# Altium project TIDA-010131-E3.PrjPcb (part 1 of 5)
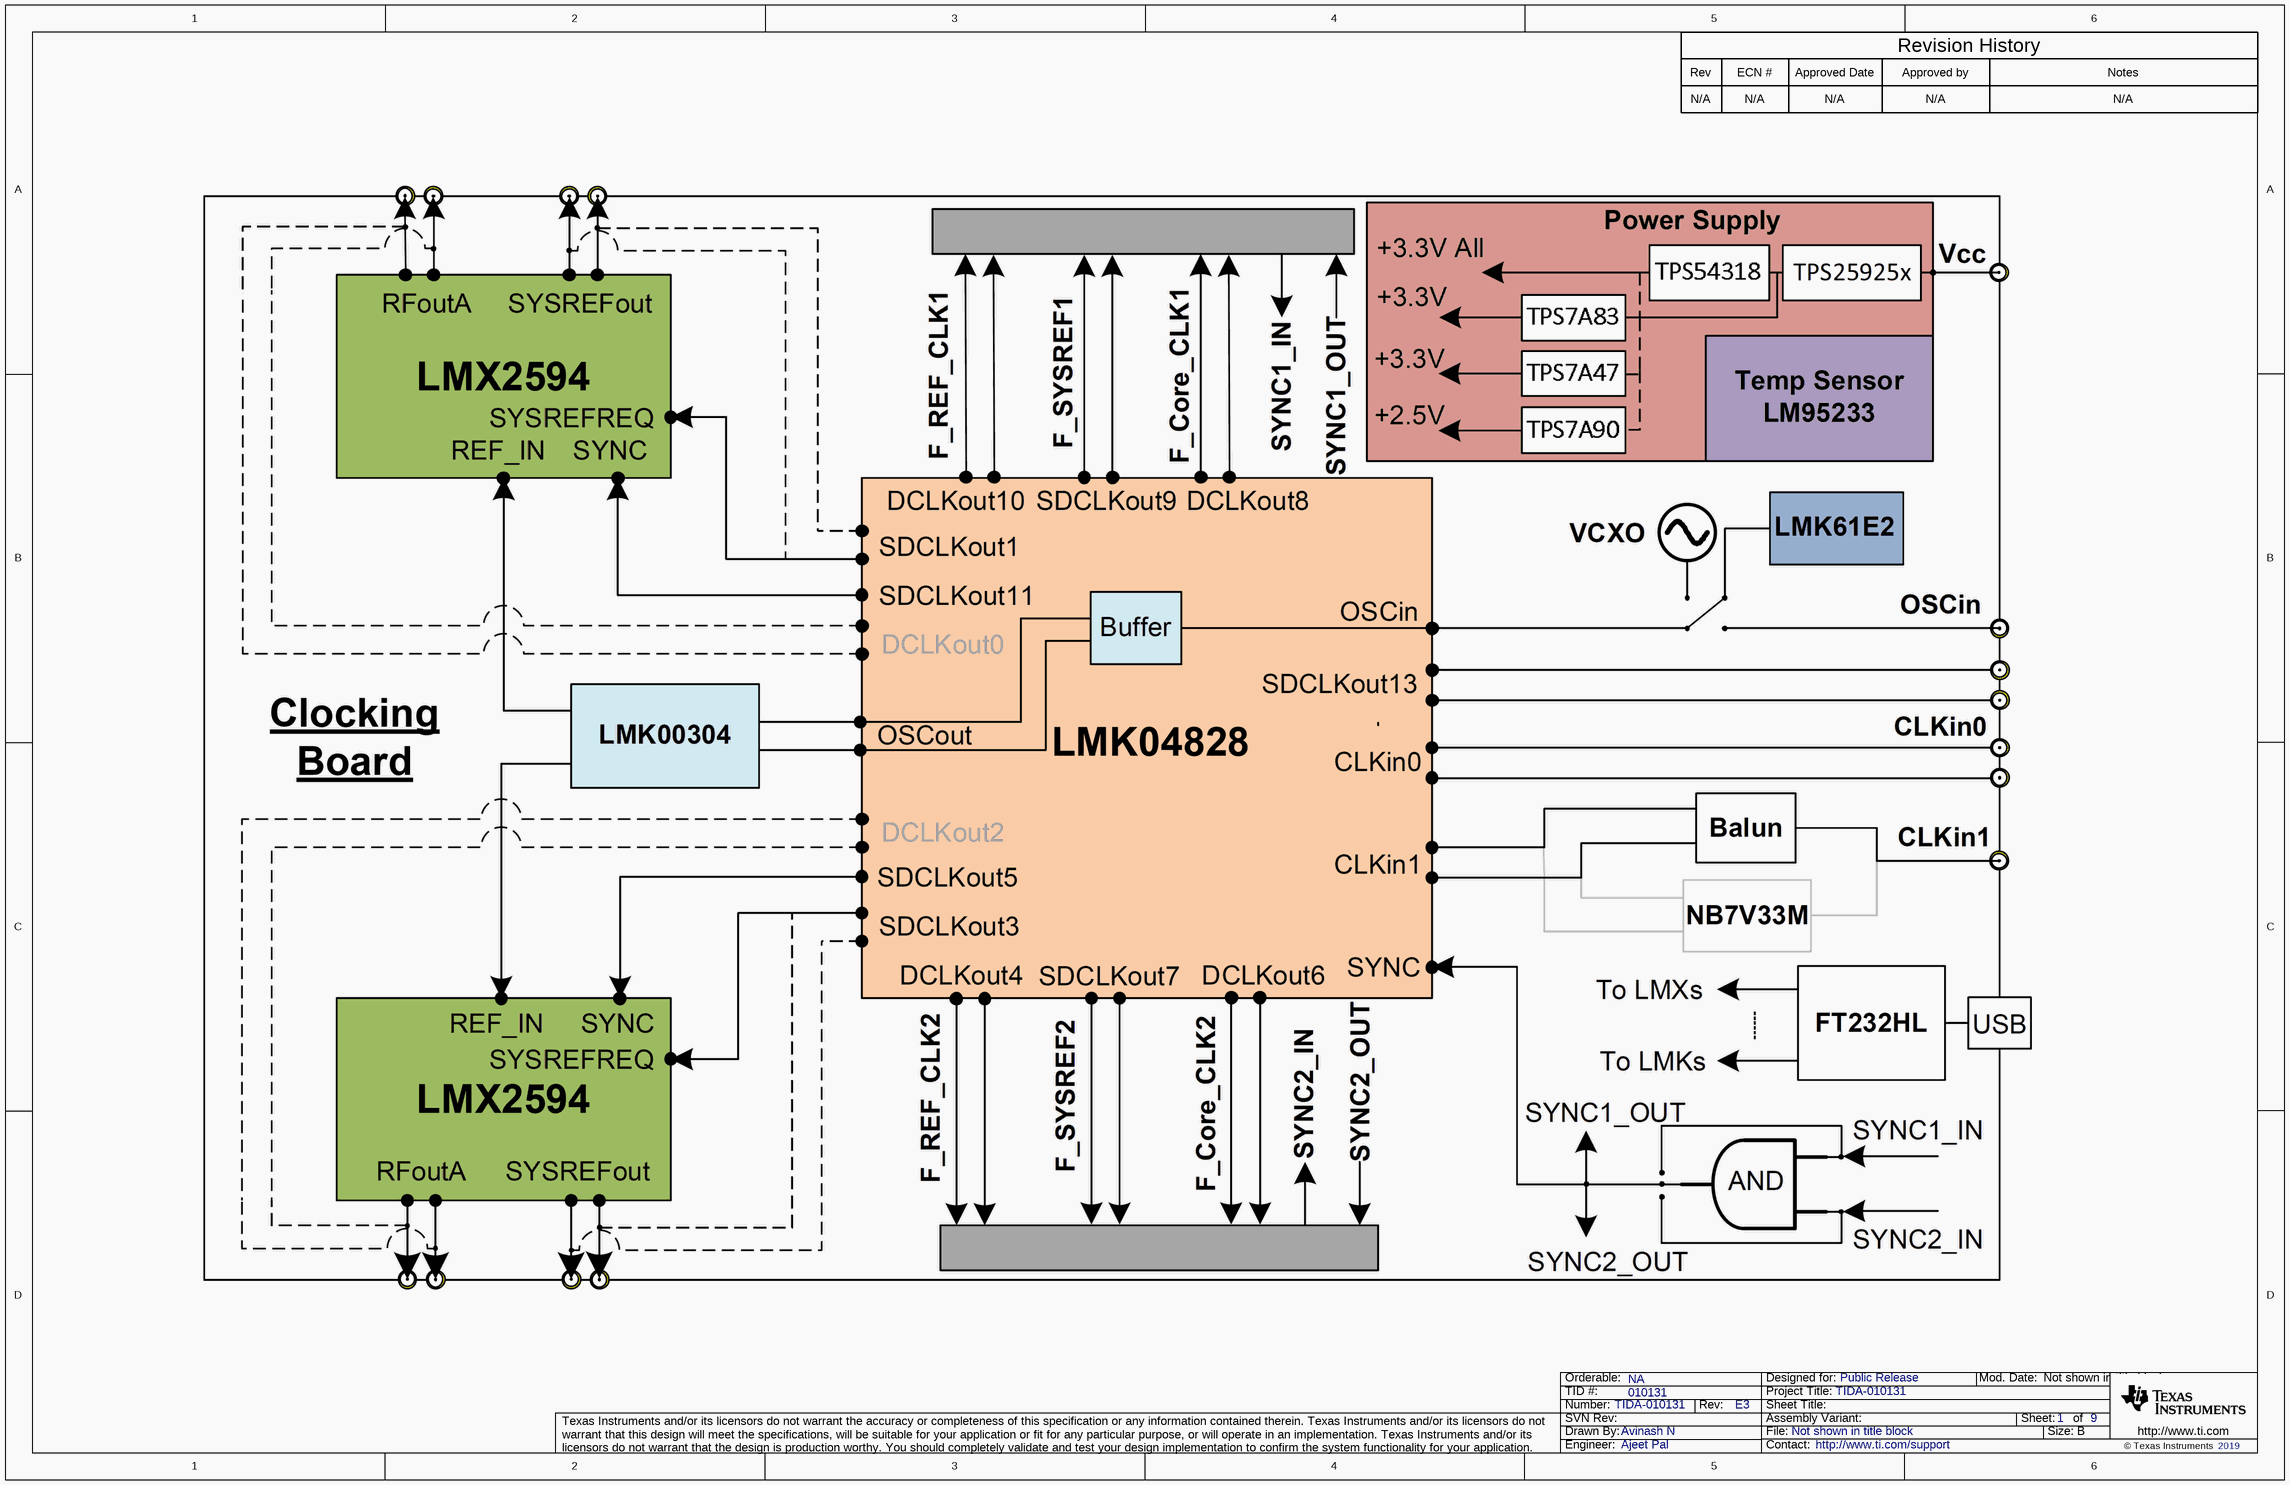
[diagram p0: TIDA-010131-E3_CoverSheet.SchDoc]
CopyrightYear: 2019; EVM_orderable: NA; PCB_Layout: Avinash N; PCB_Rev: E3; PRJ_Customer: Public Release; PRJ_Engineer: Ajeet Pal; PRJ_Number: TIDA-010131; PRJ_Title: TIDA-010131; SCH_Rev: E3; TechSupport: http://www.ti.com/support; TID: 010131
9 sheets, 759 parts. Net scope: flat (ports and power ports of the same name join across sheets).
Board file: TIDA-010131-E3.PcbDoc
Sheets:
  TIDA-010131-E3_CoverSheet.SchDoc
  TIDA-010131-E3_LMK0482x.SchDoc
  TIDA-010131-E3_LMK0482x _CLK_PWR.SchDoc
  TIDA-010131-E3_LMK00304_Buffer.SchDoc
  TIDA-010131-E3_LMX2594R_1.SchDoc
  TIDA-010131-E3_LMX2594R_2.SchDoc
  TIDA-010131-E3_USB.SchDoc
  TIDA-010131-E3_POWER SUPPLIES.SchDoc
  TIDA-010131-E3_Hardware.SchDoc

## Sheet TIDA-010131-E3_CoverSheet.SchDoc
size 431 x 279 mm; Date: Not shown in title block; ApprovedBy: Not shown in title block; CheckedBy: Not shown in title block; Author: Not shown in title block; CompanyName: Not shown in title block; DrawnBy: Avinash N; Engineer: Not shown in title block; Organization: Not shown in title block; Address1: Not shown in title block; Address2: Not shown in title block; Address3: Not shown in title block; Address4: Not shown in title block; DocumentNumber: 1; Revision: Use project parameter SCH_Rev; SheetNumber: 1; SheetTotal: 9; PageSetup: Record=PageOptions¦CenterHorizontal=True¦CenterVertical=True¦PrintScale=1.00¦XCorrection=1.00¦YCorrection=1.00¦PrintKind=0¦BorderSize=5000000¦LeftOffset=0¦BottomOffset=0¦Orientation=2¦PaperLength=1000¦PaperWidth=1000¦Scale=100¦PaperSource=15¦PrintQuality=600¦MediaType=1¦DitherType=10¦PaperKind=Letter¦PrintScaleMode=1

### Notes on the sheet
- Rev
- N/A
- ECN #
- Approved Date
- Approved by
- Revision History
- Notes

## Sheet TIDA-010131-E3_LMK0482x.SchDoc: LMK0482x
size 431 x 279 mm; Date: Not shown in title block; ApprovedBy: Not shown in title block; CheckedBy: Not shown in title block; Author: Not shown in title block; CompanyName: Not shown in title block; DrawnBy: Avinash N; Engineer: Not shown in title block; Organization: Not shown in title block; Address1: Not shown in title block; Address2: Not shown in title block; Address3: Not shown in title block; Address4: Not shown in title block; DocumentNumber: 1; Revision: Use project parameter SCH_Rev; SheetNumber: 2; SheetTotal: 9; PageSetup: Record=PageOptions¦CenterHorizontal=True¦CenterVertical=True¦PrintScale=1.00¦XCorrection=1.00¦YCorrection=1.00¦PrintKind=0¦BorderSize=5000000¦LeftOffset=0¦BottomOffset=0¦Orientation=2¦PaperLength=1000¦PaperWidth=1000¦Scale=100¦PaperSource=15¦PrintQuality=600¦MediaType=1¦DitherType=10¦PaperKind=Letter¦PrintScaleMode=1
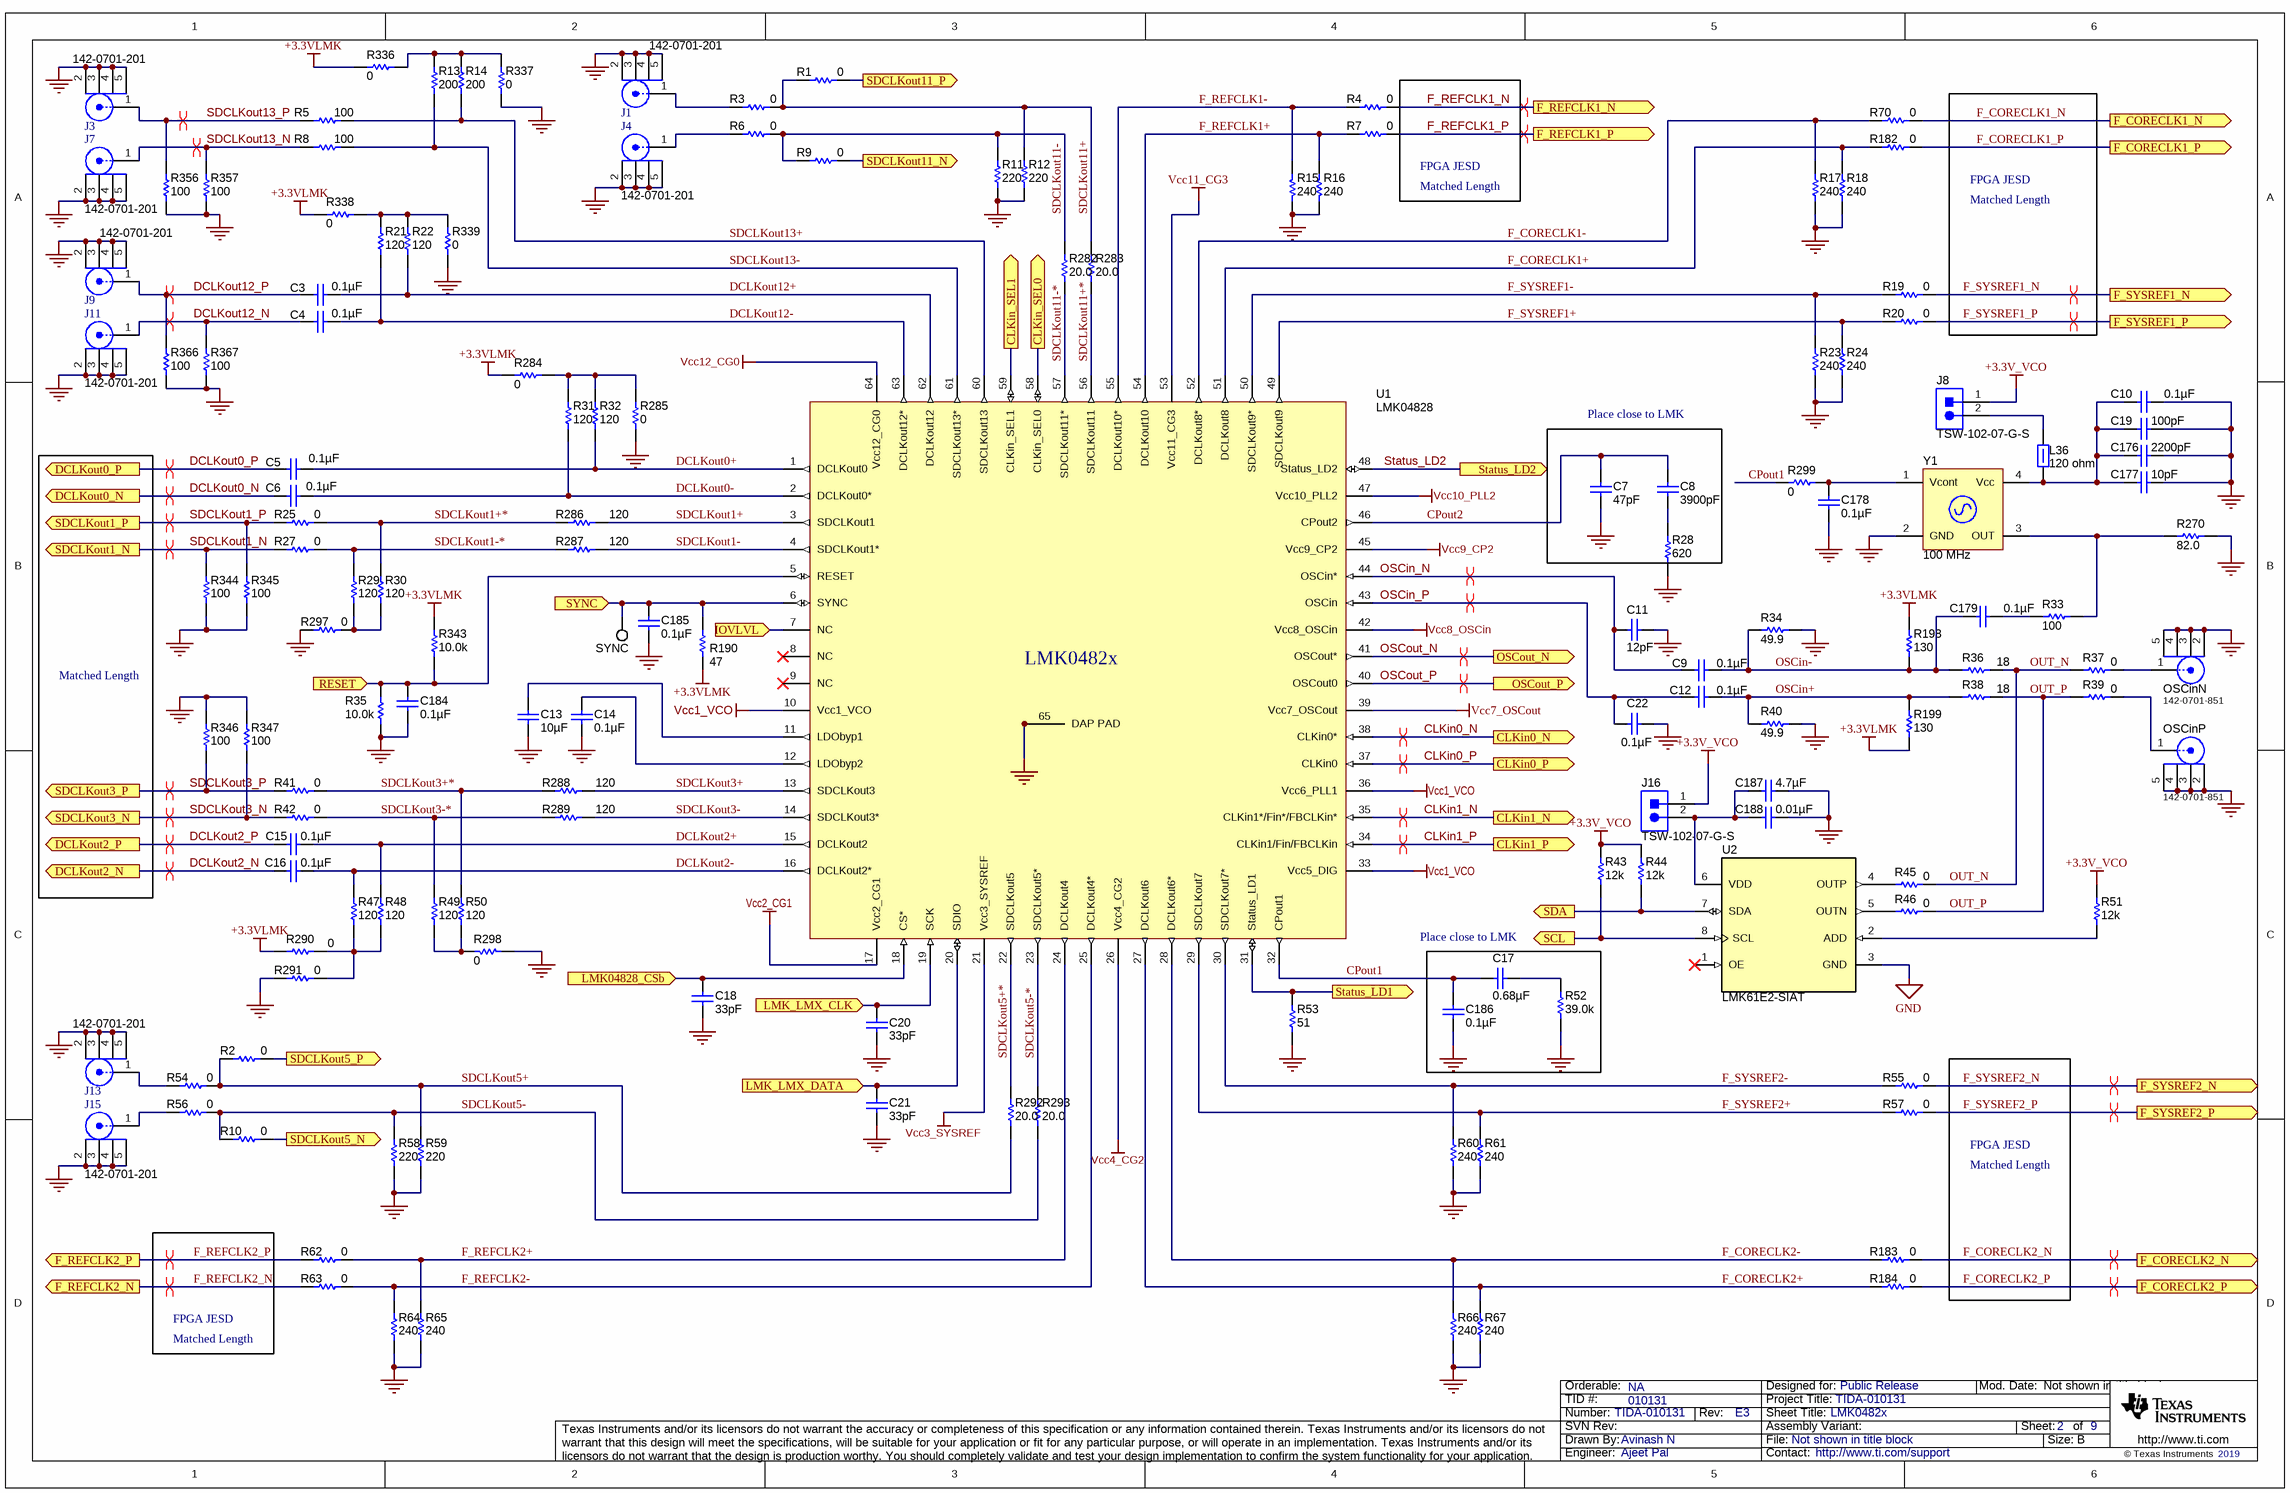
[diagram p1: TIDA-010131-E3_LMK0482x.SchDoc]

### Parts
C3  ValueDisplayed: 0.1µF  [0402]  (hidden comment: C1005X7R1E104M050BB)
C4  ValueDisplayed: 0.1µF  [0402]  (hidden comment: C1005X7R1E104M050BB)
C5  ValueDisplayed: 0.1µF  [0402]  (hidden comment: C1005X7R1E104M050BB)
C6  ValueDisplayed: 0.1µF  [0402]  (hidden comment: C1005X7R1E104M050BB)
C7  ValueDisplayed: 47pF  [0201_033]  (hidden comment: GRM0335C1E470JA01D)
C8  ValueDisplayed: 3900pF  [0201]  (hidden comment: 0201ZD392KAT2A)
C9  ValueDisplayed: 0.1µF  [0402]  (hidden comment: C1005X7R1E104M050BB)
C10  ValueDisplayed: 0.1µF  [0402]  (hidden comment: C1005X7R1E104M050BB)
C11  ValueDisplayed: 12pF  [0402]  (hidden comment: C0402C120J3GACAUTO)
C12  ValueDisplayed: 0.1µF  [0402]  (hidden comment: C1005X7R1E104M050BB)
C13  ValueDisplayed: 10µF  [0805_HV]  (hidden comment: C0805C106K8PACTU)
C14  ValueDisplayed: 0.1µF  [0603]  (hidden comment: C0603C104J3RACTU)
C15  ValueDisplayed: 0.1µF  [0402]  (hidden comment: C1005X7R1E104M050BB)
C16  ValueDisplayed: 0.1µF  [0402]  (hidden comment: C1005X7R1E104M050BB)
C17  ValueDisplayed: 0.68µF  [0402]  (hidden comment: C1005X5R1A684K050BB)
C18  ValueDisplayed: 33pF  [0603L]  (hidden comment: C0603C330J5GACTU)
C19  ValueDisplayed: 100pF  [0402]  (hidden comment: 04025A101FAT2A)
C20  ValueDisplayed: 33pF  [0603L]  (hidden comment: C0603C330J5GACTU)
C21  ValueDisplayed: 33pF  [0603L]  (hidden comment: C0603C330J5GACTU)
C22  ValueDisplayed: 0.1µF  [0402]  (hidden comment: C1005X7R1E104M050BB)
C176  ValueDisplayed: 2200pF  [0402]  (hidden comment: GRM155R71E222KA01D)
C177  ValueDisplayed: 10pF  [0402]  (hidden comment: GRM1555C1H100JA01D)
C178  ValueDisplayed: 0.1µF  [0402]  (hidden comment: C1005X7R1E104M050BB)
C179  ValueDisplayed: 0.1µF  [0402]  (hidden comment: C1005X7R1E104M050BB)
C184  ValueDisplayed: 0.1µF  [0402]  (hidden comment: C1005X7R1E104M050BB)
C185  ValueDisplayed: 0.1µF  [0402]  (hidden comment: C1005X7R1E104M050BB)
C186  ValueDisplayed: 0.1µF  [0402]  (hidden comment: C1005X7R1E104M050BB)
C187  ValueDisplayed: 4.7µF  [0402]  (hidden comment: C1005X5R0J475M050BC)
C188  ValueDisplayed: 0.01µF  [0402]  (hidden comment: GRM155R71E103KA01D)
J1  142-0701-201  [Johnson_142-0701-20x]
J3  142-0701-201  [Johnson_142-0701-20x]
J4  142-0701-201  [Johnson_142-0701-20x]
J7  142-0701-201  [Johnson_142-0701-20x]
J8  TSW-102-07-G-S  [TSW-102-07-G-S]
J9  142-0701-201  [Johnson_142-0701-20x]
J11  142-0701-201  [Johnson_142-0701-20x]
J13  142-0701-201  [Johnson_142-0701-20x]
J15  142-0701-201  [Johnson_142-0701-20x]
J16  TSW-102-07-G-S  [TSW-102-07-G-S]
L36  ValueDisplayed: 120 ohm  [0603]  (hidden comment: BLM18SG121TN1D)
OSCinN  142-0701-851  [EMERSON_142-0701-851]
OSCinP  142-0701-851  [EMERSON_142-0701-851]
R1  ValueDisplayed: 0  [0402]  (hidden comment: CRCW04020000Z0ED)
R2  ValueDisplayed: 0  [0402]  (hidden comment: CRCW04020000Z0ED)
R3  ValueDisplayed: 0  [0402]  (hidden comment: CRCW04020000Z0ED)
R4  ValueDisplayed: 0  [0402]  (hidden comment: CRCW04020000Z0ED)
R5  ValueDisplayed: 100  [0402]  (hidden comment: ERJ-2RKF1000X)
R6  ValueDisplayed: 0  [0402]  (hidden comment: CRCW04020000Z0ED)
R7  ValueDisplayed: 0  [0402]  (hidden comment: CRCW04020000Z0ED)
R8  ValueDisplayed: 100  [0402]  (hidden comment: ERJ-2RKF1000X)
R9  ValueDisplayed: 0  [0402]  (hidden comment: CRCW04020000Z0ED)
R10  ValueDisplayed: 0  [0402]  (hidden comment: CRCW04020000Z0ED)
R11  ValueDisplayed: 220  [0402]  (hidden comment: CRCW0402220RJNED)
R12  ValueDisplayed: 220  [0402]  (hidden comment: CRCW0402220RJNED)
R13  ValueDisplayed: 200  [0402]  (hidden comment: CRCW0402200RFKED)
R14  ValueDisplayed: 200  [0402]  (hidden comment: CRCW0402200RFKED)
R15  ValueDisplayed: 240  [0402]  (hidden comment: CRCW0402240RJNED)
R16  ValueDisplayed: 240  [0402]  (hidden comment: CRCW0402240RJNED)
R17  ValueDisplayed: 240  [0402]  (hidden comment: CRCW0402240RJNED)
R18  ValueDisplayed: 240  [0402]  (hidden comment: CRCW0402240RJNED)
R19  ValueDisplayed: 0  [0402]  (hidden comment: CRCW04020000Z0ED)
R20  ValueDisplayed: 0  [0402]  (hidden comment: CRCW04020000Z0ED)
R21  ValueDisplayed: 120  [0402]  (hidden comment: CRCW0402120RJNED)
R22  ValueDisplayed: 120  [0402]  (hidden comment: CRCW0402120RJNED)
R23  ValueDisplayed: 240  [0402]  (hidden comment: CRCW0402240RJNED)
R24  ValueDisplayed: 240  [0402]  (hidden comment: CRCW0402240RJNED)
R25  ValueDisplayed: 0  [0402]  (hidden comment: CRCW04020000Z0ED)
R27  ValueDisplayed: 0  [0402]  (hidden comment: CRCW04020000Z0ED)
R28  ValueDisplayed: 620  [0201]  (hidden comment: RC0201FR-07620RL)
R29  ValueDisplayed: 120  [0402]  (hidden comment: CRCW0402120RJNED)
R30  ValueDisplayed: 120  [0402]  (hidden comment: CRCW0402120RJNED)
R31  ValueDisplayed: 120  [0402]  (hidden comment: CRCW0402120RJNED)
R32  ValueDisplayed: 120  [0402]  (hidden comment: CRCW0402120RJNED)
R33  ValueDisplayed: 100  [0402]  (hidden comment: CRCW0402100RFKED)
R34  ValueDisplayed: 49.9  [0402]  (hidden comment: CRCW040249R9FKED)
R35  ValueDisplayed: 10.0k  [0402]  (hidden comment: ERJ-2RKF1002X)
R36  ValueDisplayed: 18  [0402]  (hidden comment: CRCW040218R0JNED)
R37  ValueDisplayed: 0  [0402]  (hidden comment: CRCW04020000Z0ED)
R38  ValueDisplayed: 18  [0402]  (hidden comment: CRCW040218R0JNED)
R39  ValueDisplayed: 0  [0402]  (hidden comment: CRCW04020000Z0ED)
R40  ValueDisplayed: 49.9  [0402]  (hidden comment: CRCW040249R9FKED)
R41  ValueDisplayed: 0  [0402]  (hidden comment: CRCW04020000Z0ED)
R42  ValueDisplayed: 0  [0402]  (hidden comment: CRCW04020000Z0ED)
R43  ValueDisplayed: 12k  [0402]  (hidden comment: CRCW040212K0JNED)
R44  ValueDisplayed: 12k  [0402]  (hidden comment: CRCW040212K0JNED)
R45  ValueDisplayed: 0  [0402]  (hidden comment: CRCW04020000Z0ED)
R46  ValueDisplayed: 0  [0402]  (hidden comment: CRCW04020000Z0ED)
R47  ValueDisplayed: 120  [0402]  (hidden comment: CRCW0402120RJNED)
R48  ValueDisplayed: 120  [0402]  (hidden comment: CRCW0402120RJNED)
R49  ValueDisplayed: 120  [0402]  (hidden comment: CRCW0402120RJNED)
R50  ValueDisplayed: 120  [0402]  (hidden comment: CRCW0402120RJNED)
R51  ValueDisplayed: 12k  [0402]  (hidden comment: CRCW040212K0JNED)
R52  ValueDisplayed: 39.0k  [0201]  (hidden comment: RC0201FR-0739KL)
R53  value 51  [0603L]  (hidden comment: CRCW060351R0JNEA)
R54  ValueDisplayed: 0  [0402]  (hidden comment: CRCW04020000Z0ED)
R55  ValueDisplayed: 0  [0402]  (hidden comment: CRCW04020000Z0ED)
R56  ValueDisplayed: 0  [0402]  (hidden comment: CRCW04020000Z0ED)
R57  ValueDisplayed: 0  [0402]  (hidden comment: CRCW04020000Z0ED)
R58  ValueDisplayed: 220  [0402]  (hidden comment: CRCW0402220RJNED)
R59  ValueDisplayed: 220  [0402]  (hidden comment: CRCW0402220RJNED)
R60  ValueDisplayed: 240  [0402]  (hidden comment: CRCW0402240RJNED)
R61  ValueDisplayed: 240  [0402]  (hidden comment: CRCW0402240RJNED)
R62  ValueDisplayed: 0  [0402]  (hidden comment: CRCW04020000Z0ED)
R63  ValueDisplayed: 0  [0402]  (hidden comment: CRCW04020000Z0ED)
R64  ValueDisplayed: 240  [0402]  (hidden comment: CRCW0402240RJNED)
R65  ValueDisplayed: 240  [0402]  (hidden comment: CRCW0402240RJNED)
R66  ValueDisplayed: 240  [0402]  (hidden comment: CRCW0402240RJNED)
R67  ValueDisplayed: 240  [0402]  (hidden comment: CRCW0402240RJNED)
R70  ValueDisplayed: 0  [0402]  (hidden comment: CRCW04020000Z0ED)
R182  ValueDisplayed: 0  [0402]  (hidden comment: CRCW04020000Z0ED)
R183  ValueDisplayed: 0  [0402]  (hidden comment: CRCW04020000Z0ED)
R184  ValueDisplayed: 0  [0402]  (hidden comment: CRCW04020000Z0ED)
R190  ValueDisplayed: 47  [0402]  (hidden comment: CRCW040247R0JNED)
R198  ValueDisplayed: 130  [0402]  (hidden comment: CRCW0402130RFKED)
R199  ValueDisplayed: 130  [0402]  (hidden comment: CRCW0402130RFKED)
R270  ValueDisplayed: 82.0  [0603]  (hidden comment: RC0603FR-0782RL)
R282  ValueDisplayed: 20.0  [0402]  (hidden comment: CRCW040220R0FKED)
R283  ValueDisplayed: 20.0  [0402]  (hidden comment: CRCW040220R0FKED)
R284  ValueDisplayed: 0  [0402]  (hidden comment: CRCW04020000Z0ED)
R285  ValueDisplayed: 0  [0402]  (hidden comment: CRCW04020000Z0ED)
R286  ValueDisplayed: 120  [0402]  (hidden comment: CRCW0402120RJNED)
R287  ValueDisplayed: 120  [0402]  (hidden comment: CRCW0402120RJNED)
R288  ValueDisplayed: 120  [0402]  (hidden comment: CRCW0402120RJNED)
R289  ValueDisplayed: 120  [0402]  (hidden comment: CRCW0402120RJNED)
R290  ValueDisplayed: 0  [0402]  (hidden comment: CRCW04020000Z0ED)
R291  ValueDisplayed: 0  [0402]  (hidden comment: CRCW04020000Z0ED)
R292  ValueDisplayed: 20.0  [0402]  (hidden comment: CRCW040220R0FKED)
R293  ValueDisplayed: 20.0  [0402]  (hidden comment: CRCW040220R0FKED)
R297  ValueDisplayed: 0  [0402]  (hidden comment: CRCW04020000Z0ED)
R298  ValueDisplayed: 0  [0402]  (hidden comment: CRCW04020000Z0ED)
R299  ValueDisplayed: 0  [0402]  (hidden comment: CRCW04020000Z0ED)
R336  ValueDisplayed: 0  [0402]  (hidden comment: CRCW04020000Z0ED)
R337  ValueDisplayed: 0  [0402]  (hidden comment: CRCW04020000Z0ED)
R338  ValueDisplayed: 0  [0402]  (hidden comment: CRCW04020000Z0ED)
R339  ValueDisplayed: 0  [0402]  (hidden comment: CRCW04020000Z0ED)
R343  ValueDisplayed: 10.0k  [0402]  (hidden comment: ERJ-2RKF1002X)
R344  ValueDisplayed: 100  [0402]  (hidden comment: ERJ-2RKF1000X)
R345  ValueDisplayed: 100  [0402]  (hidden comment: ERJ-2RKF1000X)
R346  ValueDisplayed: 100  [0402]  (hidden comment: ERJ-2RKF1000X)
R347  ValueDisplayed: 100  [0402]  (hidden comment: ERJ-2RKF1000X)
R356  ValueDisplayed: 100  [0402]  (hidden comment: ERJ-2RKF1000X)
R357  ValueDisplayed: 100  [0402]  (hidden comment: ERJ-2RKF1000X)
R366  ValueDisplayed: 100  [0402]  (hidden comment: ERJ-2RKF1000X)
R367  ValueDisplayed: 100  [0402]  (hidden comment: ERJ-2RKF1000X)
SYNC  5007  [Keystone5007]  (value not drawn)
U1  LMK04828  [NKD0064A]
U2  LMK61E2-SIAT  [SIA0008B]
Y1  Frequency: 100 MHz  [OSC_CVHD-950-4]  (hidden comment: CVHD-950-100.000)

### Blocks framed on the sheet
Place close to LMK: C7 C8 R28

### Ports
CLKin0_N (out), CLKin0_P (out), CLKin1_N (out), CLKin1_P (out), CLKin_SEL0 (out), CLKin_SEL1 (out), DCLKout0_N (out), DCLKout0_P (out), DCLKout2_N (out), DCLKout2_P (out), F_CORECLK1_N (out), F_CORECLK1_P (out), F_CORECLK2_N (out), F_CORECLK2_P (out), F_REFCLK1_N (out), F_REFCLK1_P (out), F_REFCLK2_N (out), F_REFCLK2_P (out), F_SYSREF1_N (out), F_SYSREF1_P (out), F_SYSREF2_N (out), F_SYSREF2_P (out), IOVLVL (in), LMK04828_CSb (in), LMK_LMX_CLK (in), LMK_LMX_DATA (in), OSCout_N (out), OSCout_P (out), RESET (in), SCL (out), SDA (out), SDCLKout1_N (out), SDCLKout1_P (out), SDCLKout3_N (out), SDCLKout3_P (out), SDCLKout5_N (out), SDCLKout5_P (out), SDCLKout11_N (out), SDCLKout11_P (out), Status_LD1 (out), Status_LD2 (out), SYNC (in)

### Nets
+3.3V_VCO: J8.1 J16.1 R43.2 R44.2 R51.1
+3.3VLMK: R190.1 R198.1 R199.1 R284.2 R290.2 R336.2 R338.2 R343.2
GND: C7.2 C10.1 C11.1 C13.2 C14.2 C18.1 C19.1 C20.1 C21.1 C22.1 C176.1 C177.1 C178.1 C184.2 C185.2 C186.1 C187.1 C188.1 J1.2 J1.3 J1.4 J1.5 J3.2 J3.3 J3.4 J3.5 J4.2 J4.3 J4.4 J4.5 J7.2 J7.3 J7.4 J7.5 J9.2 J9.3 J9.4 J9.5 J11.2 J11.3 J11.4 J11.5 J13.2 J13.3 J13.4 J13.5 J15.2 J15.3 J15.4 J15.5 OSCinN.2 OSCinN.3 OSCinN.4 OSCinN.5 OSCinP.2 OSCinP.3 OSCinP.4 OSCinP.5 R11.1 R12.1 R15.1 R16.1 R17.1 R18.1 R23.1 R24.1 R28.1 R34.1 R35.1 R40.1 R52.1 R53.1 R58.1 R59.1 R60.1 R61.1 R64.1 R65.1 R66.1 R67.1 R270.1 R285.1 R291.2 R297.2 R298.2 R337.1 R339.1 R344.1 R345.1 R346.2 R347.2 R356.1 R357.1 R366.1 R367.1 U1.65(DAP_PAD) U2.3(GND) Y1.2(GND)
Vcc1_VCO: U1.10(Vcc1_VCO) U1.33(Vcc5_DIG) U1.36(Vcc6_PLL1)
Vcc2_CG1: U1.17(Vcc2_CG1)
Vcc3_SYSREF: U1.21(Vcc3_SYSREF)
Vcc4_CG2: U1.26(Vcc4_CG2)
Vcc7_OSCout: U1.39(Vcc7_OSCout)
Vcc8_OSCin: U1.42(Vcc8_OSCin)
Vcc9_CP2: U1.45(Vcc9_CP2)
Vcc10_PLL2: U1.47(Vcc10_PLL2)
Vcc11_CG3: U1.53(Vcc11_CG3)
Vcc12_CG0: U1.64(Vcc12_CG0)
CLKin0_N: U1.38(CLKin0*) ; port CLKin0_N
CLKin0_P: U1.37(CLKin0) ; port CLKin0_P
CLKin1_N: U1.35(CLKin1*/Fin*/FBCLKin*) ; port CLKin1_N
CLKin1_P: U1.34(CLKin1/Fin/FBCLKin) ; port CLKin1_P
CLKin_SEL0: U1.58(CLKin_SEL0) ; port CLKin_SEL0
CLKin_SEL1: U1.59(CLKin_SEL1) ; port CLKin_SEL1
CPout1: C17.2 C186.2 R299.2 U1.32(CPout1)
CPout2: C7.1 C8.1 U1.46(CPout2)
DCLKout0+: C5.2 R32.2 U1.1(DCLKout0)
DCLKout0-: C6.2 R31.2 U1.2(DCLKout0*)
DCLKout0_N: C6.1 ; port DCLKout0_N
DCLKout0_P: C5.1 ; port DCLKout0_P
DCLKout2+: C15.2 R48.2 U1.15(DCLKout2)
DCLKout2-: C16.2 R47.2 U1.16(DCLKout2*)
DCLKout2_N: C16.1 ; port DCLKout2_N
DCLKout2_P: C15.1 ; port DCLKout2_P
DCLKout12+: C3.1 R22.2 U1.62(DCLKout12)
DCLKout12-: C4.1 R21.2 U1.63(DCLKout12*)
DCLKout12_N: C4.2 J11.1 R367.2
DCLKout12_P: C3.2 J9.1 R366.2
F_CORECLK1+: R18.2 R182.1 U1.51(DCLKout8)
F_CORECLK1-: R17.2 R70.1 U1.52(DCLKout8*)
F_CORECLK1_N: R70.2 ; port F_CORECLK1_N
F_CORECLK1_P: R182.2 ; port F_CORECLK1_P
F_CORECLK2+: R67.2 R184.1 U1.27(DCLKout6)
F_CORECLK2-: R66.2 R183.1 U1.28(DCLKout6*)
F_CORECLK2_N: R183.2 ; port F_CORECLK2_N
F_CORECLK2_P: R184.2 ; port F_CORECLK2_P
F_REFCLK1+: R7.1 R16.2 U1.54(DCLKout10)
F_REFCLK1-: R4.1 R15.2 U1.55(DCLKout10*)
F_REFCLK1_N: R4.2 ; port F_REFCLK1_N
F_REFCLK1_P: R7.2 ; port F_REFCLK1_P
F_REFCLK2+: R62.2 R65.2 U1.24(DCLKout4)
F_REFCLK2-: R63.2 R64.2 U1.25(DCLKout4*)
F_REFCLK2_N: R63.1 ; port F_REFCLK2_N
F_REFCLK2_P: R62.1 ; port F_REFCLK2_P
F_SYSREF1+: R20.1 R24.2 U1.49(SDCLKout9)
F_SYSREF1-: R19.1 R23.2 U1.50(SDCLKout9*)
F_SYSREF1_N: R19.2 ; port F_SYSREF1_N
F_SYSREF1_P: R20.2 ; port F_SYSREF1_P
F_SYSREF2+: R57.1 R61.2 U1.29(SDCLKout7)
F_SYSREF2-: R55.1 R60.2 U1.30(SDCLKout7*)
F_SYSREF2_N: R55.2 ; port F_SYSREF2_N
F_SYSREF2_P: R57.2 ; port F_SYSREF2_P
IOVLVL: U1.7(NC) ; port IOVLVL
LMK04828_CSb: C18.2 U1.18(CS*) ; port LMK04828_CSb
LMK_LMX_CLK: C20.2 U1.19(SCK) ; port LMK_LMX_CLK
LMK_LMX_DATA: C21.2 U1.20(SDIO) ; port LMK_LMX_DATA
OSCin+: C12.2 R38.2 R40.2 R199.2
OSCin-: C9.2 C179.2 R34.2 R36.2 R198.2
OSCin_N: C9.1 C11.2 U1.44(OSCin*)
OSCin_P: C12.1 C22.2 U1.43(OSCin)
OSCout_N: U1.41(OSCout*) ; port OSCout_N
OSCout_P: U1.40(OSCout0) ; port OSCout_P
OUT_N: R36.1 R37.1 R45.2
OUT_P: R38.1 R39.1 R46.2
RESET: C184.1 R35.2 R343.1 U1.5(RESET) ; port RESET
SCL: R43.1 U2.8(SCL) ; port SCL
SDA: R44.1 U2.7(SDA) ; port SDA
SDCLKout1+: R286.1 U1.3(SDCLKout1)
SDCLKout1+*: R25.2 R30.2 R286.2
SDCLKout1-: R287.1 U1.4(SDCLKout1*)
SDCLKout1-*: R27.2 R29.2 R287.2
SDCLKout1_N: R27.1 R344.2 ; port SDCLKout1_N
SDCLKout1_P: R25.1 R345.2 ; port SDCLKout1_P
SDCLKout3+: R288.1 U1.13(SDCLKout3)
SDCLKout3+*: R41.2 R50.2 R288.2
SDCLKout3-: R289.1 U1.14(SDCLKout3*)
SDCLKout3-*: R42.2 R49.2 R289.2
SDCLKout3_N: R42.1 R347.1 ; port SDCLKout3_N
SDCLKout3_P: R41.1 R346.1 ; port SDCLKout3_P
SDCLKout5+: R2.1 R54.2 R59.2 R292.1
SDCLKout5+*: R292.2 U1.22(SDCLKout5)
SDCLKout5-: R10.1 R56.2 R58.2 R293.1
SDCLKout5-*: R293.2 U1.23(SDCLKout5*)
SDCLKout5_N: R10.2 ; port SDCLKout5_N
SDCLKout5_P: R2.2 ; port SDCLKout5_P
SDCLKout11+: R1.1 R3.2 R12.2 R283.2
SDCLKout11+*: R283.1 U1.56(SDCLKout11)
SDCLKout11-: R6.2 R9.1 R11.2 R282.2
SDCLKout11-*: R282.1 U1.57(SDCLKout11*)
SDCLKout11_N: R9.2 ; port SDCLKout11_N
SDCLKout11_P: R1.2 ; port SDCLKout11_P
SDCLKout13+: R5.2 R14.2 U1.60(SDCLKout13)
SDCLKout13-: R8.2 R13.2 U1.61(SDCLKout13*)
SDCLKout13_N: J7.1 R8.1 R357.2
SDCLKout13_P: J3.1 R5.1 R356.2
Status_LD1: R53.2 U1.31(Status_LD1) ; port Status_LD1
Status_LD2: U1.48(Status_LD2) ; port Status_LD2
SYNC: C185.1 R190.2 SYNC.1 U1.6(SYNC) ; port SYNC
NetC8_2: C8.2 R28.2
NetC10_2: C10.2 C19.2 C176.2 C177.2 L36.1 Y1.4(Vcc)
NetC13_1: C13.1 U1.11(LDObyp1)
NetC14_1: C14.1 U1.12(LDObyp2)
NetC17_1: C17.1 R52.2
NetC178_2: C178.2 R299.1 Y1.1(Vcont)
NetC179_1: C179.1 R33.1
NetC187_2: C187.2 C188.2 J16.2 U2.6(VDD)
NetJ1_1: J1.1 R3.1
NetJ4_1: J4.1 R6.1
NetJ8_2: J8.2 L36.2
NetJ13_1: J13.1 R54.1
NetJ15_1: J15.1 R56.1
NetOSCinN_1: OSCinN.1 R37.2
NetOSCinP_1: OSCinP.1 R39.2
NetR13_1: R13.1 R14.1 R336.1 R337.2
NetR21_1: R21.1 R22.1 R338.1 R339.2
NetR29_1: R29.1 R30.1 R297.1
NetR31_1: R31.1 R32.1 R284.1 R285.2
NetR33_2: R33.2 R270.2 Y1.3(OUT)
NetR45_1: R45.1 U2.4(OUTP)
NetR46_1: R46.1 U2.5(OUTN)
NetR47_1: R47.1 R48.1 R290.1 R291.1
NetR49_1: R49.1 R50.1 R298.1
NetR51_2: R51.2 U2.2(ADD)

Not connected (* = marked no-connect by the designer): U1 8(NC)* 9(NC)*; U2 1(OE)*

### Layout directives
differential pair: CLKin0_N, CLKin0_P, CLKin1_N, CLKin1_P, DCLKout0_N, DCLKout0_P, DCLKout2_N, DCLKout2_P, DCLKout12_N, DCLKout12_P, F_CORECLK2_N, F_CORECLK2_P, F_REFCLK1_N, F_REFCLK1_P, F_REFCLK2_N, F_REFCLK2_P, F_SYSREF1_N, F_SYSREF1_P, F_SYSREF2_N, F_SYSREF2_P, OSCin_N, OSCin_P, OSCout_N, OSCout_P, SDCLKout1_N, SDCLKout1_P, SDCLKout3_N, SDCLKout3_P, SDCLKout13_N, SDCLKout13_P

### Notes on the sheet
- FPGA JESD
- Matched Length
- (near C17) Place close to LMK
- Labels drawn without touching a wire or pin: Status_LD1

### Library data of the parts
C3-C6 C9 C10 C12 C15 C16 C22 C178 C179 C184-C186 = C1005X7R1E104M050BB: CAP, CERM, 0.1 µF, 25 V, +/- 20%, X7R, 0402; Manufacturer: TDK; Polarized: N; TaMax_C: 125; TaMin_C: -55; Tolerance_%: 20; VDC_V: 25; Cap_F: 0.0000001; CompType: Capacitor; Value: 0.1uF; Value1: Unknown; Value2: 25V; U/M: EA; SizeArea_mm2: 0.5; SizeAreaWB_mm2: 3; SizeX_mm: 1; SizeZ_mm: 0.6; AEC Category: Q200
C7 = GRM0335C1E470JA01D: CAP, CERM, 47 pF, 25 V, +/- 5%, C0G/NP0, 0201; Manufacturer: MuRata; Polarized: N; CompType: Capacitor; Value: 47pF; U/M: EA; Cap_F: 0.000000000047; Tolerance_%: 5; Value1: Unknown; VDC_V: 25; Value2: 25V; TaMin_C: -55; TaMax_C: 125; Cap_Case: 0201; SizeArea_mm2: 0.18; SizeAreaWB_mm2: 2.08; SizeX_mm: 0.6; SizeY_mm: 0.3; SizeZ_mm: 0.33; AEC Category: Q200
C8 = 0201ZD392KAT2A: CAP, CERM, 3900 pF, 10 V, +/- 10%, X5R, 0201; Manufacturer: AVX; Polarized: N; CompType: Capacitor; Value: 3900pF; U/M: EA; Cap_F: 0.0000000039; Tolerance_%: 10; Value1: Unknown; Value2: 10V; TaMin_C: -55; TaMax_C: 85; SizeArea_mm2: 0.18; SizeAreaWB_mm2: 2.08; SizeX_mm: 0.6; SizeY_mm: 0.3; SizeZ_mm: 0.26; AEC Category: Q200
C11 = C0402C120J3GACAUTO: CAP, CERM, 12 pF, 25 V, +/- 5%, C0G/NP0, AEC-Q200 Grade 1, 0402; Manufacturer: Kemet; Polarized: N; CompType: Capacitor; Value: 12pF; U/M: EA; Cap_F: 0.000000000012; Tolerance_%: 5; Value1: Unknown; VDC_V: 25; Value2: 25V; TaMin_C: -55; TaMax_C: 125; SizeArea_mm2: 0.5; SizeAreaWB_mm2: 3; SizeX_mm: 1; SizeZ_mm: 0.6; AEC Category: Q200; AEC Qualified: Y
C13 = C0805C106K8PACTU: CAP, CERM, 10uF, 10V, +/-10%, X5R, 0805; Manufacturer: Kemet; Cap_Case: 0805; ESR_Ohm: 0.003; IRMS_A: 11.43; Polarized: N; TaMax_C: 85; TaMin_C: -55; Tolerance_%: 10; Cap_F: 0.00001; CompType: Capacitor; Value1: 0.003 ohm; U/M: EA
C14 = C0603C104J3RACTU: CAP, CERM, 0.1uF, 25V, +/-5%, X7R, 0603; Manufacturer: Kemet; Polarized: N; TaMax_C: 125; TaMin_C: -55; Tolerance_%: 5; VDC_V: 25; Cap_F: 0.0000001; CompType: Capacitor; Value1: Unknown; U/M: EA
C17 = C1005X5R1A684K050BB: CAP, CERM, 0.68 µF, 10 V, +/- 10%, X5R, 0402; Manufacturer: TDK; Polarized: N; CompType: Capacitor; Value: 0.68uF; U/M: EA; Cap_F: 0.00000068; Tolerance_%: 10; Value1: Unknown; Value2: 10V; TaMin_C: -55; TaMax_C: 85; SizeArea_mm2: 0.5; SizeAreaWB_mm2: 3; SizeX_mm: 1; SizeZ_mm: 0.6; AEC Category: Q200
C18 C20 C21 = C0603C330J5GACTU: CAP, CERM, 33pF, 50V, +/-5%, C0G/NP0, 0603; Manufacturer: Kemet; Cap_Case: 0603; Polarized: N; TaMax_C: 125; TaMin_C: -55; Tolerance_%: 5; VDC_V: 50; Cap_F: 0.000000000033; CompType: Capacitor; U/M: EA; Value1: Unknown
C19 = 04025A101FAT2A: CAP, CERM, 100 pF, 50 V, +/- 1%, C0G/NP0, 0402; Manufacturer: AVX; Polarized: N; CompType: Capacitor; Value: 100pF; U/M: EA; Cap_F: 0.0000000001; Tolerance_%: 1; Value1: Unknown; VDC_V: 50; Value2: 50V; TaMin_C: -55; TaMax_C: 125; SizeArea_mm2: 0.5; SizeAreaWB_mm2: 3; SizeZ_mm: 0.6; AEC Category: Q200
C176 = GRM155R71E222KA01D: CAP, CERM, 2200 pF, 25 V, +/- 10%, X7R, 0402; Manufacturer: MuRata; Polarized: N; CompType: Capacitor; Value: 2200pF; U/M: EA; Cap_F: 0.0000000022; Tolerance_%: 10; Value1: Unknown; VDC_V: 25; Value2: 25V; TaMin_C: -55; TaMax_C: 125; SizeArea_mm2: 0.5; SizeAreaWB_mm2: 3; SizeX_mm: 1; SizeZ_mm: 0.6; AEC Category: Q200
C177 = GRM1555C1H100JA01D: CAP, CERM, 10 pF, 50 V, +/- 5%, C0G/NP0, 0402; Manufacturer: MuRata; Polarized: N; CompType: Capacitor; Value: 10pF; U/M: EA; Cap_F: 0.00000000001; Tolerance_%: 5; Value1: Unknown; VDC_V: 50; Value2: 50V; TaMin_C: -55; TaMax_C: 125; SizeArea_mm2: 0.5; SizeAreaWB_mm2: 3; SizeX_mm: 1; SizeZ_mm: 0.6; AEC Category: Q200
C187 = C1005X5R0J475M050BC: CAP, CERM, 4.7 µF, 6.3 V, +/- 20%, X5R, 0402; Manufacturer: TDK; Polarized: N; CompType: Capacitor; Value: 4.7uF; U/M: EA; Cap_F: 0.0000047; Tolerance_%: 20; Value1: Unknown; VDC_V: 6.3; Value2: 6.3V; TaMin_C: -55; TaMax_C: 85; SizeArea_mm2: 0.5; SizeAreaWB_mm2: 3; SizeX_mm: 1; SizeZ_mm: 0.6; AEC Category: Q200
C188 = GRM155R71E103KA01D: CAP, CERM, 0.01 µF, 25 V, +/- 10%, X7R, 0402; Manufacturer: MuRata; Polarized: N; CompType: Capacitor; Value: 0.01uF; U/M: EA; Cap_F: 0.00000001; Tolerance_%: 10; Value1: Unknown; VDC_V: 25; Value2: 25V; TaMin_C: -55; TaMax_C: 125; SizeArea_mm2: 0.5; SizeAreaWB_mm2: 3; SizeX_mm: 1; SizeZ_mm: 0.6; AEC Category: Q200
J1 J3 J4 J7 J9 J11 J13 J15 = 142-0701-201: Connector, TH, SMA; Manufacturer: Emerson Network Power; SymbolCreator: X0208326
J8 J16 = TSW-102-07-G-S: Header, 100mil, 2x1, Gold, TH; Manufacturer: Samtec; SymbolCreator: a0412235; Pitch_mm: 2.54; Gender: Male; Shrouded: N; Row_Count: 1; Current_A: 6.3; Voltage_V: 550; Cert_CSA: Y
L36 = BLM18SG121TN1D: Ferrite Bead, 120 ohm @ 100 MHz, 3 A, 0603; Manufacturer: MuRata; Value: 120 ohm; Imax_A: 3; DCR_ohm: 0.025; Value1: 0.025 ohm; Value2: 3A; SizeAreaWB_mm2: 4.68; SizeArea_mm2: 1.28; SizeX_mm: 1.6; SizeY_mm: 0.8; SizeZ_mm: 1; ZTyp@100MHz_Ohm: 120
OSCinN OSCinP = 142-0701-851: Connector, SMT, End launch SMA 50 ohm; Manufacturer: Emerson Network Power Connectivity; U/M: EA
R1-R4 R6 R7 R9 R10 R19 R20 R25 R27 R41 R42 R54-R57 R62 R63 R70 R182-R184 R284 R285 R290 R291 R297-R299 R336-R339 = CRCW04020000Z0ED: RES, 0, 5%, 0.063 W, 0402; Manufacturer: Vishay-Dale; CompType: Resistor; Value: 0; Value_Code: 0000; Tolerance_%: 5; Power_W: 0.063; Value2: 0.063W; VDC_V: 50; TempCo: 200 ppm/C; SizeArea_mm2: 0.5; SizeX_mm: 1; SizeZ_mm: 0.6; EIA_Code: E24; U/M: EA; AEC Category: Q200
R5 R8 R344-R347 R356 R357 R366 R367 = ERJ-2RKF1000X: RES, 100, 1%, 0.1 W, 0402; Manufacturer: Panasonic; CompType: Resistor; Value: 100; Value_Code: 100R; Tolerance_%: 1; Power_W: 0.1; Value2: 0.1W; VDC_V: 50; TempCo: 100 ppm/C; SizeArea_mm2: 0.5; SizeZ_mm: 0.6; EIA_Code: E96; U/M: EA; AEC Category: Q200; Green_Lifecycle: Active; Green_REACh: Passed
R11 R12 R58 R59 = CRCW0402220RJNED: RES, 220, 5%, 0.063 W, 0402; Manufacturer: Vishay-Dale; CompType: Resistor; Value: 220; Value_Code: 220R; Tolerance_%: 5; Power_W: 0.063; Value2: 0.063W; VDC_V: 50; TempCo: 200 ppm/C; SizeArea_mm2: 0.5; SizeX_mm: 1; SizeZ_mm: 0.6; EIA_Code: E24; U/M: EA; AEC Category: Q200
R13 R14 = CRCW0402200RFKED: RES, 200, 1%, 0.063 W, 0402; Manufacturer: Vishay-Dale; CompType: Resistor; Value: 200; Value_Code: 200R; Tolerance_%: 1; Power_W: 0.063; Value2: 0.063W; VDC_V: 50; TempCo: 100 ppm/C; SizeArea_mm2: 0.5; SizeZ_mm: 0.6; EIA_Code: E96; U/M: EA; AEC Category: Q200; Green_Lifecycle: Active; Green_REACh: Passed
R15-R18 R23 R24 R60 R61 R64-R67 = CRCW0402240RJNED: RES, 240, 5%, 0.063 W, 0402; Manufacturer: Vishay-Dale; CompType: Resistor; Value: 240; Value_Code: 240R; Tolerance_%: 5; Power_W: 0.063; Value2: 0.063W; VDC_V: 50; TempCo: 200 ppm/C; SizeArea_mm2: 0.5; SizeX_mm: 1; SizeZ_mm: 0.6; EIA_Code: E24; U/M: EA; AEC Category: Q200
R21 R22 R29-R32 R47-R50 R286-R289 = CRCW0402120RJNED: RES, 120, 5%, 0.063 W, 0402; Manufacturer: Vishay-Dale; CompType: Resistor; Value: 120; Value_Code: 120R; Tolerance_%: 5; Power_W: 0.063; Value2: 0.063W; VDC_V: 50; TempCo: 200 ppm/C; SizeArea_mm2: 0.5; SizeX_mm: 1; SizeZ_mm: 0.6; EIA_Code: E24; U/M: EA; AEC Category: Q200
R28 = RC0201FR-07620RL: RES, 620, 1%, 0.05 W, 0201; Manufacturer: Yageo America; CompType: Resistor; Value: 620; Value_Code: 620R; Tolerance_%: 1; Power_W: 0.05; Value2: 0.05W; VDC_V: 25; TempCo: 200 ppm/C; SizeArea_mm2: 0.18; SizeX_mm: 0.6; SizeY_mm: 0.3; SizeZ_mm: 0.26; U/M: EA; AEC Category: Q200; AEC Qualified: N
R33 = CRCW0402100RFKED: RES, 100, 1%, 0.063 W, 0402; Manufacturer: Vishay-Dale; CompType: Resistor; Value: 100; Value_Code: 100R; Tolerance_%: 1; Power_W: 0.063; Value2: 0.063W; VDC_V: 50; TempCo: 100 ppm/C; EIA_Code: E96; U/M: EA; AEC Category: Q200; SizeArea_mm2: 0.5; SizeZ_mm: 0.6
R34 R40 = CRCW040249R9FKED: RES, 49.9, 1%, 0.063 W, 0402; Manufacturer: Vishay-Dale; CompType: Resistor; Value: 49.9; Value_Code: 49R9; Tolerance_%: 1; Power_W: 0.063; Value2: 0.063W; VDC_V: 50; TempCo: 100 ppm/C; EIA_Code: E96; U/M: EA; AEC Category: Q200
R35 R343 = ERJ-2RKF1002X: RES, 10.0 k, 1%, 0.1 W, 0402; Manufacturer: Panasonic; CompType: Resistor; Value: 10.0k; Res_ohm: 10000; Value_Code: 10k0; Tolerance_%: 1; Power_W: 0.1; Value2: 0.1W; VDC_V: 50; TempCo: 100 ppm/C; SizeArea_mm2: 0.5; SizeZ_mm: 0.6; EIA_Code: E96; U/M: EA; AEC Category: Q200
R36 R38 = CRCW040218R0JNED: RES, 18, 5%, 0.063 W, 0402; Manufacturer: Vishay-Dale; CompType: Resistor; Value: 18; Value_Code: 18R0; Tolerance_%: 5; Power_W: 0.063; Value2: 0.063W; VDC_V: 50; TempCo: 200 ppm/C; EIA_Code: E24; U/M: EA; AEC Category: Q200
R37 R39 R45 R46 = CRCW04020000Z0ED: RES, 0, 5%, 0.063 W, 0402; Manufacturer: Vishay-Dale; CompType: Resistor; Value: 0; Value_Code: 0000; Tolerance_%: 5; Power_W: 0.063; Value2: 0.063W; VDC_V: 50; TempCo: 200 ppm/C; EIA_Code: E24; U/M: EA; AEC Category: Q200
R43 R44 R51 = CRCW040212K0JNED: RES, 12 k, 5%, 0.063 W, 0402; Manufacturer: Vishay-Dale; CompType: Resistor; Value: 12k; Res_ohm: 12000; Value_Code: 12k0; Tolerance_%: 5; Power_W: 0.063; Value2: 0.063W; VDC_V: 50; TempCo: 200 ppm/C; EIA_Code: E24; U/M: EA; AEC Category: Q200
R52 = RC0201FR-0739KL: RES, 39.0 k, 1%, 0.05 W, 0201; Manufacturer: Yageo America; CompType: Resistor; Value: 39.0k; Res_ohm: 39000; Value_Code: 39k0; Tolerance_%: 1; Power_W: 0.05; Value2: 0.05W; VDC_V: 25; TempCo: 200 ppm/C; SizeArea_mm2: 0.18; SizeX_mm: 0.6; SizeY_mm: 0.3; SizeZ_mm: 0.26; U/M: EA; AEC Category: Q200; AEC Qualified: N
R53 = CRCW060351R0JNEA: RES, 51 ohm, 5%, 0.1W, 0603; Manufacturer: Vishay-Dale; CompType: Resistor; Tolerance_%: 5; VDC_V: 75; Power_W: 0.1; Value_Code: 51R0; EIA_Code: E24; TempCo: 200 ppm/C; U/M: EA
R190 = CRCW040247R0JNED: RES, 47, 5%, 0.063 W, 0402; Manufacturer: Vishay-Dale; CompType: Resistor; Value: 47; Value_Code: 47R0; Tolerance_%: 5; Power_W: 0.063; Value2: 0.063W; VDC_V: 50; TempCo: 200 ppm/C; SizeArea_mm2: 0.5; SizeX_mm: 1; SizeZ_mm: 0.6; EIA_Code: E24; U/M: EA; AEC Category: Q200
R198 R199 = CRCW0402130RFKED: RES, 130, 1%, 0.063 W, 0402; Manufacturer: Vishay-Dale; CompType: Resistor; Value: 130; Value_Code: 130R; Tolerance_%: 1; Power_W: 0.063; Value2: 0.063W; VDC_V: 50; TempCo: 100 ppm/C; SizeArea_mm2: 0.5; SizeZ_mm: 0.6; EIA_Code: E96; U/M: EA; AEC Category: Q200
R270 = RC0603FR-0782RL: RES, 82.0, 1%, 0.1 W, 0603; Manufacturer: Yageo America; CompType: Resistor; Value: 82.0; Res_ohm: 82; Value_Code: 82R0; Tolerance_%: 1; Power_W: 0.1; Value2: 0.1W; VDC_V: 150; TempCo: 200 ppm/C; SizeArea_mm2: 1.28; SizeX_mm: 1.6; SizeY_mm: 0.8; U/M: EA; AEC Category: Q200
R282 R283 R292 R293 = CRCW040220R0FKED: RES, 20.0, 1%, 0.063 W, 0402; Manufacturer: Vishay-Dale; CompType: Resistor; Value: 20.0; Res_ohm: 20; Value_Code: 20R0; Tolerance_%: 1; Power_W: 0.063; Value2: 0.063W; VDC_V: 50; TempCo: 100 ppm/C; SizeArea_mm2: 0.5; SizeZ_mm: 0.6; EIA_Code: E96; U/M: EA; AEC Category: Q200
SYNC = 5007: Test Point, Compact, White, TH; Manufacturer: Keystone; CompType: Test Point Loop; U/M: EA
U1 = LMK04828: Manufacturer: Texas Instruments; PartNumber: LMK04828BISQ
U2 = LMK61E2-SIAR: Ultra-Low Jitter Programmable Oscillator with Internal EEPROM, SIA0008B; Manufacturer: Texas Instruments; SymbolCreator: Altium; CompType: IC; U/M: EA
Y1 = CVHD-950-100.000: VCXO, 100 MHz, 3.3V, SMD; Manufacturer: Crystek Corporation; SymbolCreator: a0412235; CompType: Oscillator; U/M: EA; TaMin_C: 0; TaMax_C: 70; Frequency Stability: ±20ppm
